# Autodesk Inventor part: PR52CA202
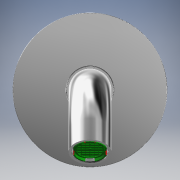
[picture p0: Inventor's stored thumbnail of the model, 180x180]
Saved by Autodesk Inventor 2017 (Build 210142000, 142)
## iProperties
Created: 2021-04
Part Number: PR52CA202
Material: Generico
Document SubType Name: Modeling
Designer: PIZZERA
Density: 1 g/cm^3
Appearance: Default
Author: PIZZERA
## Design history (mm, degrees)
feature "Base3"
node "Solido1"
node "Solido4"
